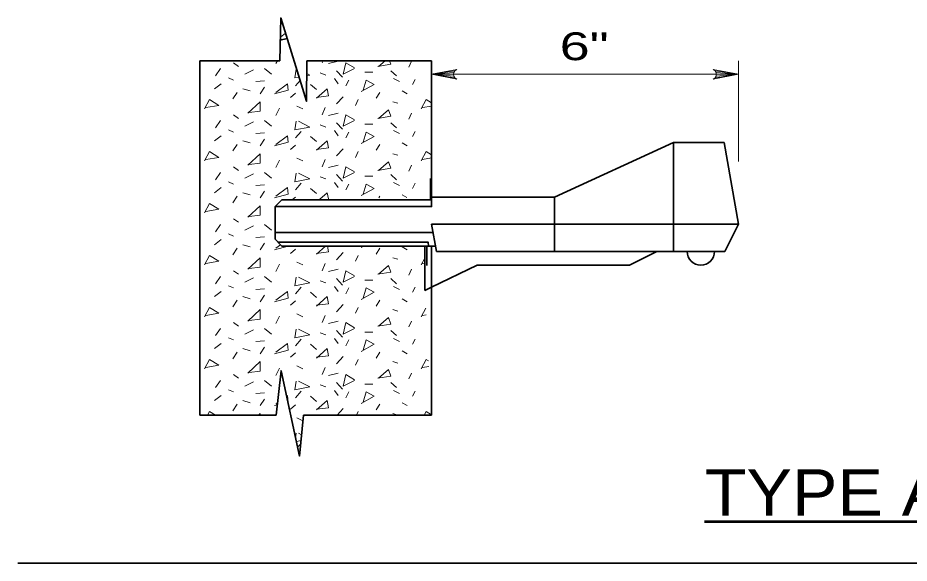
# Model space of a CAD drawing. Extents: x 15 to 140, y -57 to 117.
# Drawn here: x 15.07 to 47.78, y 57.95 to 77.95 of the extents above; entities that cross this region are included whole.
import ezdxf
from ezdxf.enums import TextEntityAlignment as Align

# ---------------------------------------------------------------- set-up
doc = ezdxf.new("R2010")
doc.units = 0
doc.header["$LTSCALE"] = 0.41
for name, color, linetype, lineweight in [('1', 7, 'Continuous', 35), ('10', 7, 'Continuous', 13), ('12', 7, 'Continuous', 53), ('13', 7, 'Continuous', 53), ('6', 7, 'Continuous', 13)]:
    doc.layers.add(name, color=color, linetype=linetype, lineweight=lineweight)

msp = doc.modelspace()

# ---------------------------------------------------------------- linework, layer by layer
at = {"layer": '1'}
for p, q in [((24.704, 77.122), (24.9551, 77.1881)), ((21.7517, 63.3749), (21.7517, 76.3749)), ((21.7517, 76.3749), (24.6899, 76.3749)), ((25.6803, 76.3749), (30.2517, 76.3749)), ((30.2517, 71.0249), (30.2517, 76.3749)), ((39.1266, 73.3749), (34.7634, 71.3749)), ((39.1266, 73.3797), (39.1266, 69.3797)), ((40.9844, 73.3749), (39.1266, 73.3749)), ((41.5134, 70.3749), (40.9844, 73.3749)), ((30.2092, 71.2749), (30.2092, 72.0499)), ((34.7634, 71.3749), (30.2517, 71.3749)), ((34.7634, 71.3749), (34.7634, 69.3749)), ((30.2517, 71.0249), (24.5134, 71.0249)), ((24.5134, 71.0249), (24.5134, 69.8249)), ((30.2517, 71.2749), (24.7634, 71.2749)), ((41.5134, 70.3749), (30.2517, 70.3749)), ((30.2517, 70.3749), (30.4392, 69.3749)), ((41.5134, 70.3749), (41.0134, 69.3749)), ((30.3087, 70.071), (24.5134, 70.071)), ((24.5134, 69.8249), (24.7634, 69.5749)), ((30.4017, 69.5749), (24.7634, 69.5749)), ((30.0017, 69.5749), (30.0017, 67.9493)), ((30.074, 69.5749), (30.074, 68.8623)), ((30.2517, 63.3749), (30.2517, 69.5749)), ((41.0134, 69.3749), (30.4392, 69.3749)), ((38.5134, 69.3749), (37.5134, 68.8749)), ((37.5134, 68.8749), (31.9301, 68.8749)), ((21.7517, 63.3749), (24.5564, 63.3749)), ((25.552, 63.3749), (30.2517, 63.3749)), ((140.4342, 57.946), (15.0728, 57.946))]:
    msp.add_line(p, q, dxfattribs=at)
for points in [[(24.5134, 71.0249), (24.7634, 71.2749), (30.2517, 71.2749), (30.2517, 71.0249)], [(24.6174, 69.7162), (30.1344, 69.7162), (30.1396, 69.5749), (24.7634, 69.5749)]]:
    msp.add_lwpolyline(points, close=True, dxfattribs=at)
msp.add_lwpolyline([(30.0017, 67.9493), (30.2517, 68.0693), (31.9301, 68.8749)], dxfattribs=at)
msp.add_arc((40.1346, 69.3749), 0.5, 180, 0, dxfattribs=at)
at = {"layer": '10'}
for p, q in [((24.895, 77.3817), (24.7062, 77.2401)), ((41.5134, 72.6834), (41.5134, 76.3749)), ((30.2517, 75.8749), (41.5134, 75.8749))]:
    msp.add_line(p, q, dxfattribs=at)
at = {"layer": '10', "lineweight": 35}
msp.add_line((25.3387, 62.1962), (25.4519, 62.3235), dxfattribs=at)
for points in [[(24.6899, 76.3749), (24.7195, 77.9467), (25.6689, 74.89), (25.6803, 76.3749)], [(24.5564, 63.3749), (24.7295, 65.0007), (25.409, 61.8729), (25.552, 63.3749)]]:
    msp.add_lwpolyline(points, dxfattribs=at)
at = {"layer": '10'}
for points in [[(30.2517, 75.8749), (31.1838, 76.0496), (31.112, 75.9999), (31.0749, 75.9374), (31.0642, 75.8749), (31.0749, 75.8124), (31.112, 75.7499), (31.1838, 75.7001), (30.2517, 75.8749), (31.112, 75.7499), (31.0749, 75.8124), (30.2517, 75.8749), (31.0642, 75.8749), (31.0749, 75.9374), (30.2517, 75.8749), (31.112, 75.9999)], [(41.5134, 75.8749), (40.5813, 75.7001), (40.6531, 75.7499), (40.6902, 75.8124), (40.7009, 75.8749), (40.6902, 75.9374), (40.6531, 75.9999), (40.5813, 76.0496), (41.5134, 75.8749), (40.6531, 75.9999), (40.6902, 75.9374), (41.5134, 75.8749), (40.7009, 75.8749), (40.6902, 75.8124), (41.5134, 75.8749), (40.6531, 75.7499)]]:
    msp.add_lwpolyline(points, dxfattribs=at)
at = {"layer": '12'}
msp.add_line((40.2691, 59.4762), (49.1839, 59.4762), dxfattribs=at)
at = {"layer": '6'}
for p, q in [((22.983, 76.2985), (23.1683, 76.1661)), ((23.5374, 76.3749), (23.5125, 76.3514)), ((24.5451, 76.272), (24.5965, 76.3749)), ((26.2701, 76.3749), (26.2395, 76.2985)), ((26.822, 76.3514), (26.4778, 76.272)), ((28.5482, 76.3749), (28.3046, 76.1661)), ((29.4166, 76.1396), (29.5225, 76.3514)), ((22.5064, 76.0867), (22.3211, 75.8219)), ((23.7243, 76.0337), (23.4066, 75.8749)), ((24.1214, 76.0867), (24.3862, 75.8749)), ((26.1601, 75.9278), (26.3719, 75.8484)), ((26.769, 76.0073), (26.9808, 75.769)), ((27.8016, 75.9543), (28.0928, 75.9543)), ((28.7547, 76.0073), (28.9665, 75.8219)), ((22.7977, 75.7425), (22.983, 75.6631)), ((23.8037, 75.6101), (24.1214, 75.6366)), ((25.2599, 75.4513), (25.4338, 75.6469)), ((26.6896, 75.716), (26.822, 75.5307)), ((27.2191, 75.6631), (27.1132, 75.4513)), ((28.8606, 75.716), (29.0724, 75.6101)), ((29.549, 75.5042), (29.6549, 75.6896)), ((22.5329, 75.5307), (22.2946, 75.3454)), ((23.3272, 75.3454), (23.5919, 75.2659)), ((23.9626, 75.16), (24.1214, 75.3983)), ((25.8159, 75.5042), (26.0277, 75.3189)), ((29.1783, 75.2659), (29.3636, 75.16)), ((30.2517, 75.3566), (30.2373, 75.3454)), ((23.1154, 75.213), (22.9565, 74.9747)), ((25.0746, 75.0277), (25.2599, 75.1865)), ((27.0073, 75.0541), (26.769, 74.7894)), ((27.5633, 74.9482), (27.4574, 74.7364)), ((28.2252, 75.0012), (28.3576, 75.213)), ((24.5451, 74.3658), (24.6774, 74.6305)), ((25.3128, 74.7099), (25.5247, 74.6041)), ((26.3454, 74.657), (26.2395, 74.3922)), ((28.8341, 74.8688), (29.0194, 74.8159)), ((30.2517, 74.7124), (29.9196, 74.657)), ((22.983, 74.3922), (23.1683, 74.2599)), ((26.822, 74.4452), (26.4778, 74.3658)), ((29.4166, 74.2334), (29.5225, 74.4452)), ((22.5064, 74.1804), (22.3211, 73.9157)), ((23.7243, 74.1275), (23.4066, 73.9686)), ((24.1214, 74.1804), (24.3862, 73.9686)), ((26.1601, 74.0216), (26.3719, 73.9422)), ((26.769, 74.101), (26.9808, 73.8627)), ((27.8016, 74.0481), (28.0928, 74.0481)), ((28.7547, 74.101), (28.9665, 73.9157)), ((22.5329, 73.6244), (22.2946, 73.4391)), ((22.7977, 73.8362), (22.983, 73.7568)), ((23.8037, 73.7039), (24.1214, 73.7304)), ((25.2599, 73.545), (25.4717, 73.7833)), ((25.8159, 73.598), (26.0277, 73.4126)), ((26.6896, 73.8098), (26.822, 73.6244)), ((27.2191, 73.7568), (27.1132, 73.545)), ((28.8606, 73.8098), (29.0724, 73.7039)), ((29.549, 73.598), (29.6549, 73.7833)), ((23.1154, 73.3067), (22.9565, 73.0685)), ((23.3272, 73.4391), (23.5919, 73.3597)), ((23.9626, 73.2538), (24.1214, 73.4921)), ((25.0746, 73.1214), (25.2599, 73.2803)), ((28.2252, 73.0949), (28.3576, 73.3067)), ((29.1783, 73.3597), (29.3636, 73.2538)), ((30.2517, 73.4503), (30.2373, 73.4391)), ((27.0073, 73.1479), (26.769, 72.8831)), ((27.5633, 73.042), (27.4574, 72.8302)), ((28.8341, 72.9626), (29.0194, 72.9096)), ((24.5451, 72.4595), (24.6774, 72.7243)), ((25.3128, 72.8037), (25.5247, 72.6978)), ((26.3454, 72.7507), (26.2395, 72.486)), ((30.2517, 72.8061), (29.9196, 72.7507)), ((22.983, 72.486), (23.1683, 72.3536)), ((26.822, 72.5389), (26.4778, 72.4595)), ((29.4166, 72.3271), (29.5225, 72.5389)), ((22.5064, 72.2742), (22.3211, 72.0094)), ((23.7243, 72.2212), (23.4066, 72.0624)), ((24.1214, 72.2742), (24.3862, 72.0624)), ((26.1601, 72.1153), (26.3719, 72.0359)), ((26.769, 72.1948), (26.9808, 71.9565)), ((27.8016, 72.1418), (28.0928, 72.1418)), ((28.7547, 72.1948), (28.9665, 72.0094)), ((22.5329, 71.7182), (22.2946, 71.5329)), ((22.7977, 71.93), (22.983, 71.8506)), ((23.8037, 71.7976), (24.1214, 71.8241)), ((25.2599, 71.6388), (25.4717, 71.8771)), ((25.8159, 71.6917), (26.0277, 71.5064)), ((26.6896, 71.9035), (26.822, 71.7182)), ((27.2191, 71.8506), (27.1132, 71.6388)), ((28.8606, 71.9035), (29.0724, 71.7976)), ((29.549, 71.6917), (29.6549, 71.8771)), ((23.1154, 71.4005), (22.9565, 71.1622)), ((23.3272, 71.5329), (23.5919, 71.4534)), ((23.9626, 71.3475), (24.1214, 71.5858)), ((25.1525, 71.282), (25.2599, 71.374)), ((28.3195, 71.3397), (28.3576, 71.4005)), ((29.1783, 71.4534), (29.3447, 71.3584)), ((30.2517, 71.5441), (30.2373, 71.5329)), ((24.5134, 71.0249), (24.7634, 71.2749)), ((22.5064, 70.3679), (22.3211, 70.1032)), ((22.983, 70.5797), (23.1683, 70.4474)), ((23.7243, 70.315), (23.4066, 70.1561)), ((24.1214, 70.3679), (24.3862, 70.1561)), ((22.7977, 70.0237), (22.983, 69.9443)), ((22.5329, 69.8119), (22.2946, 69.6266)), ((23.8037, 69.8914), (24.1214, 69.9179)), ((23.9626, 69.4413), (24.1214, 69.6796)), ((23.1154, 69.4942), (22.9565, 69.256)), ((23.3272, 69.6266), (23.5919, 69.5472)), ((24.7159, 69.6224), (24.5451, 69.4942)), ((25.0746, 69.3089), (25.2599, 69.4678)), ((26.3651, 69.5749), (26.0277, 69.2824)), ((27.0073, 69.3354), (26.769, 69.0706)), ((27.6692, 69.5207), (27.7667, 69.5749)), ((27.7489, 69.5749), (27.7486, 69.5737)), ((28.2252, 69.2824), (28.3576, 69.4942)), ((29.1783, 69.5472), (29.3636, 69.4413)), ((27.5633, 69.2295), (27.4574, 69.0177)), ((28.8341, 69.1501), (29.0194, 69.0971)), ((29.8667, 68.8853), (30.0017, 69.1361)), ((24.5451, 68.647), (24.6774, 68.9118)), ((25.3128, 68.9912), (25.5247, 68.8853)), ((26.3454, 68.9382), (26.2395, 68.6735)), ((26.822, 68.7264), (26.4778, 68.647)), ((29.4166, 68.5146), (29.5225, 68.7264)), ((30.0017, 68.9519), (29.9196, 68.9382)), ((22.5064, 68.4617), (22.3211, 68.1969)), ((22.983, 68.6735), (23.1683, 68.5411)), ((23.7243, 68.4087), (23.4066, 68.2499)), ((24.1214, 68.4617), (24.3862, 68.2499)), ((26.769, 68.3823), (26.9808, 68.144)), ((28.7547, 68.3823), (28.9665, 68.1969)), ((22.7977, 68.1175), (22.983, 68.0381)), ((25.2599, 67.8263), (25.4717, 68.0646)), ((26.1601, 68.3028), (26.3719, 68.2234)), ((26.6896, 68.091), (26.822, 67.9057)), ((27.2191, 68.0381), (27.1132, 67.8263)), ((27.8016, 68.3293), (28.0928, 68.3293)), ((28.8606, 68.091), (29.0724, 67.9851)), ((29.549, 67.8792), (29.6549, 68.0646)), ((22.5329, 67.9057), (22.2946, 67.7204)), ((23.3272, 67.7204), (23.5919, 67.6409)), ((23.8037, 67.9851), (24.1214, 68.0116)), ((23.9626, 67.535), (24.1214, 67.7733)), ((25.8159, 67.8792), (26.0277, 67.6939)), ((23.1154, 67.588), (22.9565, 67.3497)), ((25.0746, 67.4027), (25.2599, 67.5615)), ((27.0073, 67.4291), (26.769, 67.1644)), ((28.2252, 67.3762), (28.3576, 67.588)), ((29.1783, 67.6409), (29.3636, 67.535)), ((25.3128, 67.0849), (25.5247, 66.9791)), ((27.5633, 67.3232), (27.4574, 67.1114)), ((28.8341, 67.2438), (29.0194, 67.1909)), ((29.8667, 66.9791), (30.0374, 67.2961)), ((30.0506, 67.0538), (29.9196, 67.032)), ((22.983, 66.7672), (23.1683, 66.6349)), ((24.5451, 66.7408), (24.6774, 67.0055)), ((26.3454, 67.032), (26.2395, 66.7672)), ((26.822, 66.8202), (26.4778, 66.7408)), ((29.4166, 66.6084), (29.5225, 66.8202)), ((22.5064, 66.5554), (22.3211, 66.2907)), ((23.7243, 66.5025), (23.4066, 66.3436)), ((24.1214, 66.5554), (24.3862, 66.3436)), ((26.1601, 66.3966), (26.3719, 66.3172)), ((26.769, 66.476), (26.9808, 66.2377)), ((27.8016, 66.4231), (28.0928, 66.4231)), ((28.7547, 66.476), (28.9665, 66.2907)), ((22.7977, 66.2112), (22.983, 66.1318)), ((23.8037, 66.0789), (24.1214, 66.1054)), ((25.2599, 65.92), (25.4717, 66.1583)), ((26.6896, 66.1848), (26.822, 65.9994)), ((27.2191, 66.1318), (27.1132, 65.92)), ((28.8606, 66.1848), (29.0724, 66.0789)), ((29.549, 65.973), (29.6549, 66.1583)), ((22.5329, 65.9994), (22.2946, 65.8141)), ((23.3272, 65.8141), (23.5919, 65.7347)), ((23.9626, 65.6288), (24.1214, 65.8671)), ((25.8159, 65.973), (26.0277, 65.7876)), ((23.1154, 65.6817), (22.9565, 65.4435)), ((25.0746, 65.4964), (25.2599, 65.6553)), ((27.0073, 65.5229), (26.769, 65.2581)), ((27.5633, 65.417), (27.4574, 65.2052)), ((28.2252, 65.4699), (28.3576, 65.6817)), ((29.1783, 65.7347), (29.3636, 65.6288)), ((24.5451, 64.8345), (24.6774, 65.0993)), ((25.3128, 65.1787), (25.5247, 65.0728)), ((26.3454, 65.1257), (26.2395, 64.861)), ((28.8341, 65.3376), (29.0194, 65.2846)), ((30.1539, 65.1648), (29.9196, 65.1257)), ((22.983, 64.861), (23.1683, 64.7286)), ((26.822, 64.9139), (26.4778, 64.8345)), ((29.4166, 64.7021), (29.5225, 64.9139)), ((22.5064, 64.6492), (22.3211, 64.3844)), ((23.7243, 64.5962), (23.4066, 64.4374)), ((24.1214, 64.6492), (24.3862, 64.4374)), ((26.1601, 64.4903), (26.3719, 64.4109)), ((26.769, 64.5698), (26.9808, 64.3315)), ((27.8016, 64.5168), (28.0928, 64.5168)), ((28.7547, 64.5698), (28.9665, 64.3844)), ((22.7977, 64.305), (22.983, 64.2256)), ((23.8037, 64.1726), (24.1214, 64.1991)), ((25.2599, 64.0138), (25.4717, 64.2521)), ((26.6896, 64.2785), (26.822, 64.0932)), ((27.2191, 64.2256), (27.1132, 64.0138)), ((28.8606, 64.2785), (29.0724, 64.1726)), ((29.549, 64.0667), (29.6549, 64.2521)), ((22.5329, 64.0932), (22.2946, 63.9079)), ((23.1154, 63.7755), (22.9565, 63.5372)), ((23.3272, 63.9079), (23.5919, 63.8284)), ((23.9626, 63.7225), (24.1214, 63.9608)), ((24.6038, 63.8195), (24.5451, 63.7755)), ((25.8159, 64.0667), (26.0277, 63.8814)), ((28.2252, 63.5637), (28.3576, 63.7755)), ((29.1783, 63.8284), (29.3636, 63.7225)), ((24.4921, 63.7225), (24.5964, 63.75)), ((25.0746, 63.5902), (25.2599, 63.749)), ((27.0073, 63.6166), (26.7897, 63.3749)), ((27.5633, 63.5107), (27.4954, 63.3749)), ((25.3128, 63.2724), (25.5247, 63.1666)), ((28.8341, 63.4313), (29.0194, 63.3784)), ((25.2864, 62.7165), (25.26, 62.5585)), ((25.4837, 62.6575), (25.3658, 62.7165)), ((25.2923, 62.41), (25.4632, 62.4425))]:
    msp.add_line(p, q, dxfattribs=at)
for points in [[(27.4309, 76.0867), (27.0073, 75.8749), (27.1132, 76.2985), (27.4309, 76.1132)], [(28.2781, 76.1661), (28.7547, 76.2455), (28.7116, 76.3749)], [(25.2864, 76.0602), (25.2334, 75.7425), (25.3946, 75.7732)], [(25.6761, 75.8268), (25.7894, 75.8484), (25.6767, 75.9048)], [(27.6692, 75.2395), (28.1457, 75.5042), (27.8545, 75.6631), (27.7486, 75.2924)], [(24.4921, 75.16), (24.9951, 75.2924), (24.9687, 75.5307), (24.5451, 75.213)], [(26.0277, 75.0277), (26.4778, 75.0806), (26.4248, 75.3454), (26.0277, 75.0012)], [(21.924, 74.6041), (22.1093, 74.9482), (22.4535, 74.7364), (21.9769, 74.657)], [(29.8667, 74.6041), (30.052, 74.9482), (30.2517, 74.8253)], [(23.5654, 74.4717), (23.9626, 74.5246), (23.9626, 74.8688), (23.5125, 74.4452)], [(28.2781, 74.2599), (28.7547, 74.3393), (28.6753, 74.5776), (28.3046, 74.2599)], [(27.4309, 74.1804), (27.0073, 73.9686), (27.1132, 74.3922), (27.4309, 74.2069)], [(25.2864, 74.154), (25.2334, 73.8362), (25.7894, 73.9422), (25.3658, 74.154)], [(24.4921, 73.2538), (24.9951, 73.3862), (24.9687, 73.6244), (24.5451, 73.3067)], [(27.6692, 73.3332), (28.1457, 73.598), (27.8545, 73.7568), (27.7486, 73.3862)], [(26.0277, 73.1214), (26.4778, 73.1744), (26.4248, 73.4391), (26.0277, 73.0949)], [(21.924, 72.6978), (22.1093, 73.042), (22.4535, 72.8302), (21.9769, 72.7507)], [(23.5654, 72.5654), (23.9626, 72.6184), (23.9626, 72.9626), (23.5125, 72.5389)], [(29.8667, 72.6978), (30.052, 73.042), (30.2517, 72.9191)], [(28.2781, 72.3536), (28.7547, 72.433), (28.6753, 72.6713), (28.3046, 72.3536)], [(27.4309, 72.2742), (27.0073, 72.0624), (27.1132, 72.486), (27.4309, 72.3007)], [(25.2864, 72.2477), (25.2334, 71.93), (25.7894, 72.0359), (25.3658, 72.2477)], [(24.4921, 71.3475), (24.9951, 71.4799), (24.9687, 71.7182), (24.5451, 71.4005)], [(27.6692, 71.427), (28.1457, 71.6917), (27.8545, 71.8506), (27.7486, 71.4799)], [(26.4702, 71.306), (26.4248, 71.5329), (26.1564, 71.3003)], [(21.924, 70.7916), (22.1093, 71.1357), (22.4535, 70.9239), (21.9769, 70.8445)], [(23.5654, 70.6592), (23.9626, 70.7121), (23.9626, 71.0563), (23.5125, 70.6327)], [(24.4921, 69.4413), (24.9951, 69.5737), (24.995, 69.5749)], [(26.0277, 69.3089), (26.4778, 69.3619), (26.4352, 69.5749)], [(21.924, 68.8853), (22.1093, 69.2295), (22.4535, 69.0177), (21.9769, 68.9382)], [(23.5654, 68.7529), (23.9626, 68.8059), (23.9626, 69.1501), (23.5125, 68.7264)], [(28.2781, 68.5411), (28.7547, 68.6205), (28.6753, 68.8588), (28.3046, 68.5411)], [(25.2864, 68.4352), (25.2334, 68.1175), (25.7894, 68.2234), (25.3658, 68.4352)], [(27.4309, 68.4617), (27.0073, 68.2499), (27.1132, 68.6735), (27.4309, 68.4882)], [(27.6692, 67.6145), (28.1457, 67.8792), (27.8545, 68.0381), (27.7486, 67.6674)], [(24.4921, 67.535), (24.9951, 67.6674), (24.9687, 67.9057), (24.5451, 67.588)], [(26.0277, 67.4027), (26.4778, 67.4556), (26.4248, 67.7204), (26.0277, 67.3762)], [(21.924, 66.9791), (22.1093, 67.3232), (22.4535, 67.1114), (21.9769, 67.032)], [(23.5654, 66.8467), (23.9626, 66.8996), (23.9626, 67.2438), (23.5125, 66.8202)], [(27.4309, 66.5554), (27.0073, 66.3436), (27.1132, 66.7672), (27.4309, 66.5819)], [(28.2781, 66.6349), (28.7547, 66.7143), (28.6753, 66.9526), (28.3046, 66.6349)], [(25.2864, 66.529), (25.2334, 66.2112), (25.7894, 66.3172), (25.3658, 66.529)], [(27.6692, 65.7082), (28.1457, 65.973), (27.8545, 66.1318), (27.7486, 65.7612)], [(24.4921, 65.6288), (24.9951, 65.7612), (24.9687, 65.9994), (24.5451, 65.6817)], [(26.0277, 65.4964), (26.4778, 65.5494), (26.4248, 65.8141), (26.0277, 65.4699)], [(21.924, 65.0728), (22.1093, 65.417), (22.4535, 65.2052), (21.9769, 65.1257)], [(29.8667, 65.0728), (30.052, 65.417), (30.1432, 65.3609)], [(23.5654, 64.9404), (23.9626, 64.9934), (23.9626, 65.3376), (23.5125, 64.9139)], [(27.4309, 64.6492), (27.0073, 64.4374), (27.1132, 64.861), (27.4309, 64.6757)], [(28.2781, 64.7286), (28.7547, 64.808), (28.6753, 65.0463), (28.3046, 64.7286)], [(25.2864, 64.6227), (25.2334, 64.305), (25.7894, 64.4109), (25.3658, 64.6227)], [(27.6692, 63.802), (28.1457, 64.0667), (27.8545, 64.2256), (27.7486, 63.8549)], [(24.9793, 63.8507), (24.9951, 63.8549), (24.9687, 64.0932), (24.9325, 64.0661)], [(26.0277, 63.5902), (26.4778, 63.6431), (26.4248, 63.9079), (26.0277, 63.5637)], [(22.0361, 63.3749), (22.1093, 63.5107), (22.3301, 63.3749)], [(29.9788, 63.3749), (30.052, 63.5107), (30.251, 63.3883)], [(23.9626, 63.3749), (23.9626, 63.4313), (23.9026, 63.3749)]]:
    msp.add_lwpolyline(points, dxfattribs=at)

# ---------------------------------------------------------------- texts
at = {"layer": '12', "width": 1.1}
msp.add_text('TYPE A', height=1.7, dxfattribs=at).set_placement((44.7265, 59.6887), align=Align.CENTER)
at = {"layer": '13', "width": 1.45}
msp.add_text('6"', height=1.02, dxfattribs=at).set_placement((35.8551, 76.3937), align=Align.CENTER)

doc.saveas('drawing.dxf')
